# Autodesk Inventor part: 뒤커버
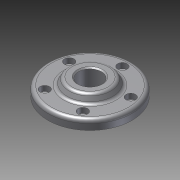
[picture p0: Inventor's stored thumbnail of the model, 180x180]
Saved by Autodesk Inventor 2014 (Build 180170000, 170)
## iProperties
Company: 한국ATC센터
Created: 2014-03
Part Number: 뒤커버
Document SubType Name: Modeling
Designer: KYOUNG IL JANG
Density: 1 g/cm^3
Material: 일반
Appearance: 기본값
Author: KYOUNG IL JANG
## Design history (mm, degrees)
sketch "스케치1"
  geometry: C1 r 20 at (0, 0); C2 r 35 at (0, 0); 1 further point
  constraints: 2 centre point, 2 coincident
  dimensions: "d0" = 40 diameter of C1; "d1" = 70 diameter of C2
extrude "돌출1" new body sketch "스케치1" distance "d2" = 5; taper "d3" = 0 deg
extrude "돌출2" join sketch "스케치1" distance "d4" = 8; taper "d5" = 0 deg
sketch "스케치2"
  geometry: C1 r 20 at (0, 0); 1 further point
  constraints: 1 centre point, 1 coincident
  dimensions: "d6" = 40 diameter of C1
extrude "돌출3" join sketch "스케치2" distance "d7" = 6; taper "d8" = -30 deg
sketch "스케치3"
  geometry: 2 further points
  constraints: 1 vertical alignment
  dimensions: "d9" = 27 distance of point (0, 0) point (0, 27)
hole "구멍1" sketch "스케치3" at (0, 27) diameter "d10" = 4.5; stored, may be unused: countersink angle "d14" = 90 deg, drill point angle "d16" = 118 deg; dims "d11" = 6, "d12" = 8, "d13" = 4.4, "d15" = 8
hole "구멍2" diameter "d22" = 19; stored, may be unused: countersink angle "d26" = 90 deg, drill point angle "d28" = 118 deg; dims "d20" = 10, "d21" = 10, "d23" = 6, "d24" = 30, "d25" = 3, "d27" = 8
fillet "모깎기1" dims "d29" = 3
chamfer "모따기1" distance "d30" = 1; stored, may be unused: second distance "d31" = 2, angle "d32" = 45 deg
node "솔리드1"
pattern_circular "원형 패턴1" dims angle "d18" = 360 deg
